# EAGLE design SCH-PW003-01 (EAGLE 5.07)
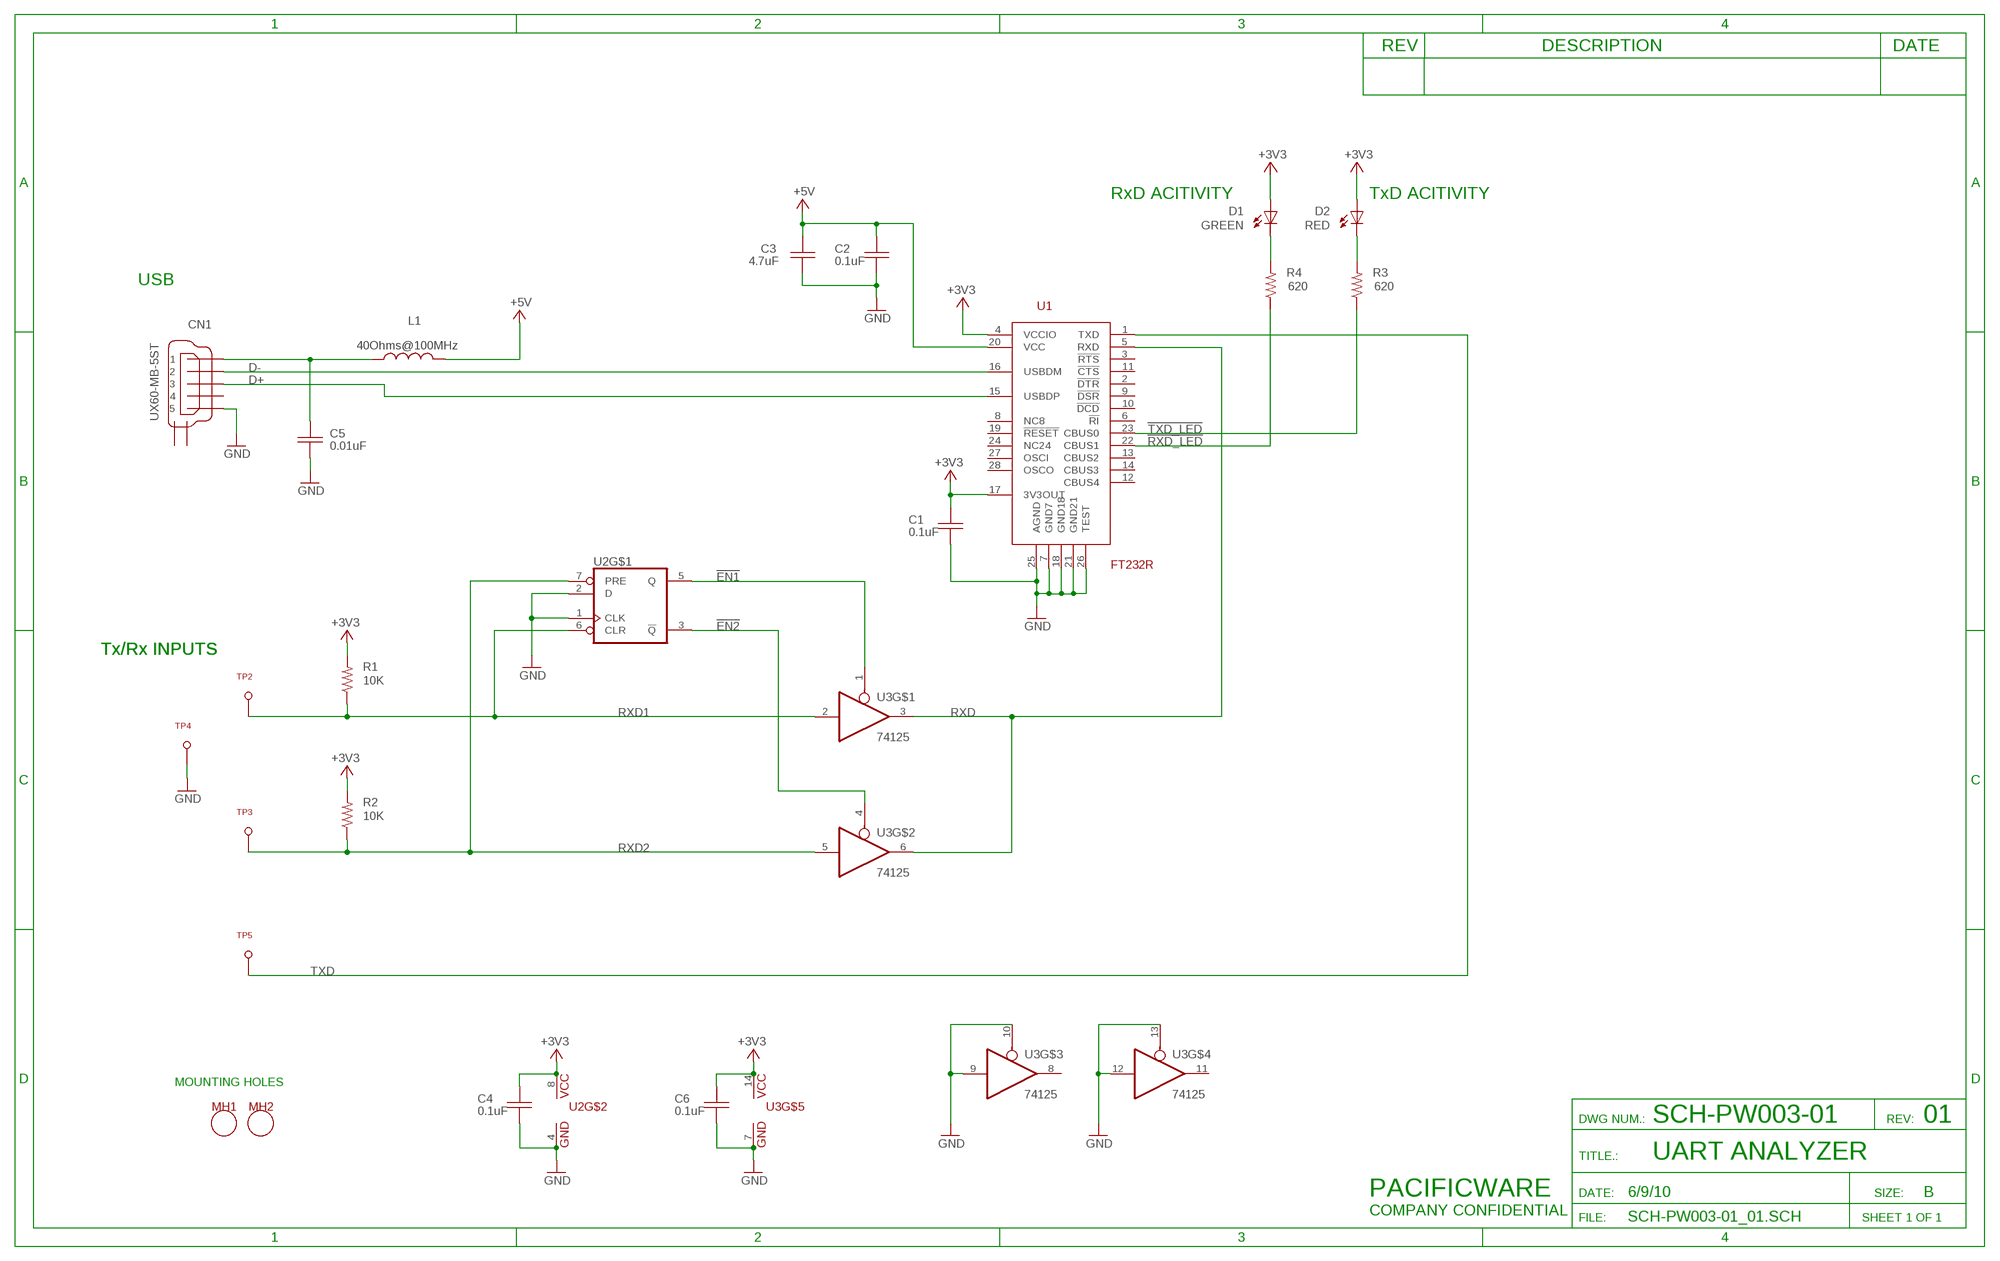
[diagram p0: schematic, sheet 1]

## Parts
C1  0.1uF  CAP-0805  [C0805]
C2  0.1uF  CAP-0805  [C0805]
C3  4.7uF  CAP-0805  [C0805]
C4  0.1uF  CAP-0805  [C0805]
C5  0.01uF  CAP-0805  [C0805]
C6  0.1uF  CAP-0805  [C0805]
CN1  UX60-MB-5ST  [UX60-MB-5ST]
D1  GREEN  LED0805  [0805LED]
D2  RED  LED0805  [0805LED]
L1  40Ohms@100MHz  IND-0805  [R0805]
MH1  HOLE_MTG_125NP  [HOLE_125NP]
MH2  HOLE_MTG_125NP  [HOLE_125NP]
R1  10K  RES-0805  [R0805]
R2  10K  RES-0805  [R0805]
R3  620  RES-0805  [R0805]
R4  620  RES-0805  [R0805]
TP2  TP_039  [HOLE_039_P]
TP3  TP_039  [HOLE_039_P]
TP4  TP_039  [HOLE_039_P]
TP5  TP_039  [HOLE_039_P]
U1  FT232R  [SSOP28]
U2  NL17SZ74  [US8]
U3  74125  [TSSOP14]

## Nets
!EN1: U2.5(Q) U3.1(OE)
!EN2: U2.3(!Q) U3.4(OE)
!RXD_LED: R4.1 U1.22(CBUS1)
!TXD_LED: R3.1 U1.23(CBUS0)
+3V3 [15mil]: C1.1 C4.1 C6.1 D1.1(A) D2.1(A) R1.2 R2.2 U1.4(VCCIO) U1.17(3V3OUT) U2.8(VCC) U3.14(VCC)
+5V [15mil]: C2.1 C3.1 L1.2 U1.20(VCC)
D+: CN1.3 U1.15(USBDP)
D-: CN1.2 U1.16(USBDM)
GND: C1.2 C2.2 C3.2 C4.2 C5.2 C6.2 CN1.5 TP4.1 U1.7(GND7) U1.18(GND18) U1.21(GND21) U1.25(AGND) U1.26(TEST) U2.1(CLK) U2.2(D) U2.4(GND) U3.7(GND) U3.9(I) U3.10(OE) U3.12(I) U3.13(OE)
N$1: C5.1 CN1.1 L1.1
N$2: D1.2(C) R4.2
N$5: D2.2(C) R3.2
RXD: U1.5(RXD) U3.3(O) U3.6(O)
RXD1: R1.1 TP2.1 U2.6(CLR) U3.2(I)
RXD2: R2.1 TP3.1 U2.7(PRE) U3.5(I)
TXD: TP5.1 U1.1(TXD)
Unconnected: CN1.4 CN1.6 CN1.7 U1.2(!DTR) U1.3(!RTS) U1.6(!RI) U1.8(NC8) U1.9(!DSR) U1.10(!DCD) U1.11(!CTS) U1.12(CBUS4) U1.13(CBUS2) U1.14(CBUS3) U1.19(!RESET) U1.24(NC24) U1.27(OSCI) U1.28(OSCO) U3.8(O) U3.11(O)

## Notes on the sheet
- REV | DESCRIPTION | DATE
- RxD ACITIVITY | TxD ACITIVITY
- USB
- Tx/Rx INPUTS | Tx/Rx INPUTS
- MOUNTING HOLES
- DWG NUM.: | SCH-PW003-01 | REV: | 01
- TITLE.: | UART ANALYZER
- PACIFICWARE | DATE: | 6/9/10 | SIZE: | B
- COMPANY CONFIDENTIAL
- FILE: | SCH-PW003-01_01.SCH | SHEET 1 OF 1

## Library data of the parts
C1-C6 = Pacificware:CAP-0805
CN1 = Pacificware:UX60-MB-5ST
D1 D2 = Pacificware:LED0805
L1 = Pacificware:IND-0805
MH1 MH2 = Pacificware:HOLE_MTG_125NP
R1-R4 = Pacificware:RES-0805
TP2-TP5 = Pacificware:TP_039
U1 = Pacificware:FT232R: FTDI FT232R, USB UART ICm, SSOP28
U2 = Pacificware:NL17SZ74: Single Gate D-FlopFlop
U3 = Pacificware:74125

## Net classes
1 20mil: width 0.508 mm
2 15mil: width 0.381 mm

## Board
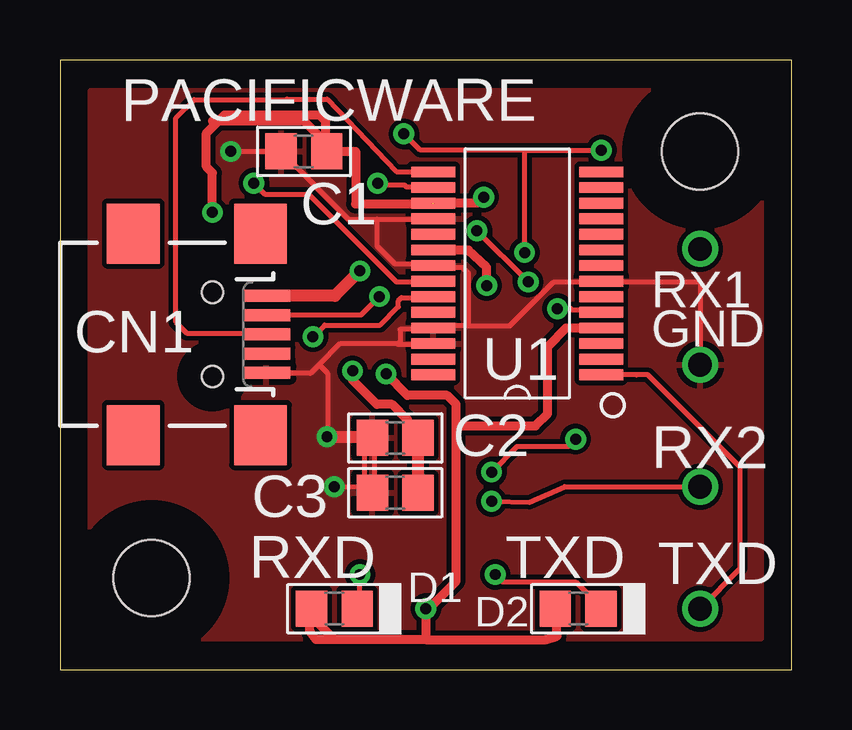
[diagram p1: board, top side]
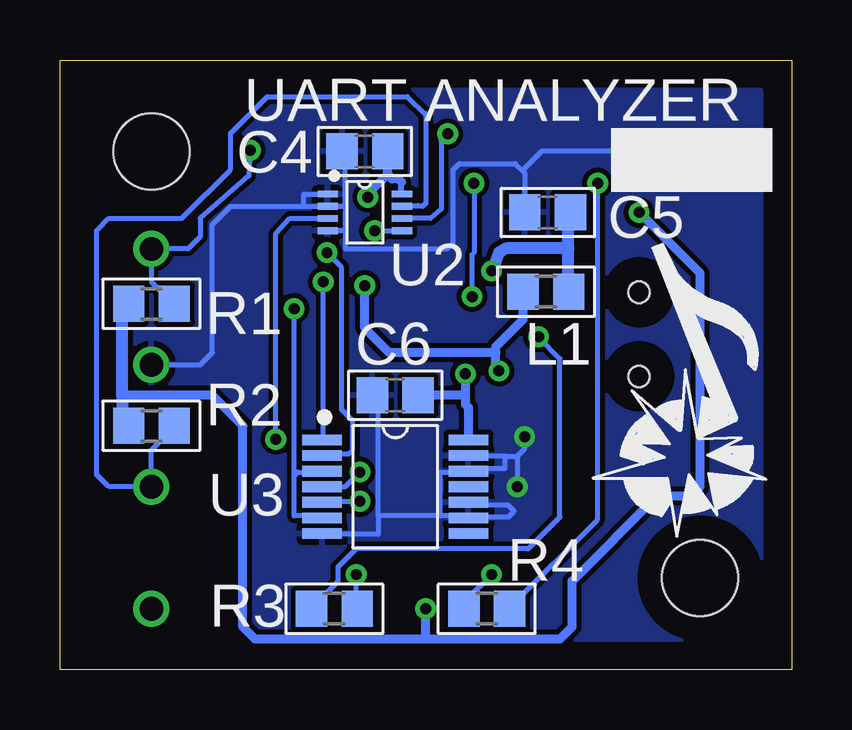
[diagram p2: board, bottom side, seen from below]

Size 30.48 x 25.4 mm. Coordinates in mm from the lower left corner, seen from the top.
Outline: 0,0 30.48,0 30.48,25.4 0,25.4 0,0
Copper layers (1*16): Top 0.035mm / dielectric 1.5mm / Bottom 0.035mm
Design rules "default *": minimum track width 8mil, minimum drill 18mil, track to track 8mil, track to pad 8mil, pad to pad 8mil, via to via 8mil, smd to smd 8mil, copper to edge 40mil, drill to drill 8mil, minimum pad ring 10mil, minimum via ring 8mil, stop-mask expansion 4mil, vias tented up to drill 0mil, thermal gap 10mil

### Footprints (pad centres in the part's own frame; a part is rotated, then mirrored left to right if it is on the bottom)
C0805 = smd 1.3 x 1.5: 1 -0.95,0; 2 0.95,0
UX60-MB-5ST = smd 2 x 0.5: 1 2.25,1.6; 2 2.25,0.8; 3 2.25,0; 4 2.25,-0.8; 5 2.25,-1.6 | smd 2.2 x 2.5: 6 -3.3,-4.2; 7 -3.3,4.2; 8 2,4.2; 9 2,-4.2 | hole 0.889: 0,1.753; 0,-1.753
0805LED = smd 1.3 x 1.5: 1 -0.95,0; 2 0.95,0
R0805 = smd 1.3 x 1.5: 1 -0.95,0; 2 0.95,0
HOLE_125NP = hole 3.175: 0,0
HOLE_039_P = drill 0.991 round: 1 0,0
SSOP28 = smd 0.45 x 1.82: 1 -4.225,-3.5; 2 -3.575,-3.5; 3 -2.925,-3.5; 4 -2.275,-3.5; 5 -1.625,-3.5; 6 -0.975,-3.5; 7 -0.325,-3.5; 8 0.325,-3.5; 9 0.975,-3.5; 10 1.625,-3.5; 11 2.275,-3.5; 12 2.925,-3.5; 13 3.575,-3.5; 14 4.225,-3.5; 15 4.225,3.5; 16 3.575,3.5; 17 2.925,3.5; 18 2.275,3.5; 19 1.625,3.5; 20 0.975,3.5; 21 0.325,3.5; 22 -0.325,3.5; 23 -0.975,3.5; 24 -1.625,3.5; 25 -2.275,3.5; 26 -2.925,3.5; 27 -3.575,3.5; 28 -4.225,3.5
US8 = smd 0.279 x 0.838: 1 -0.762,-1.549; 2 -0.254,-1.549; 3 0.254,-1.549; 4 0.762,-1.549; 5 0.762,1.549; 6 0.254,1.549; 7 -0.254,1.549; 8 -0.762,1.549
TSSOP14 = smd 0.45 x 1.65: 1 -1.95,-3.05; 2 -1.3,-3.05; 3 -0.65,-3.05; 4 0,-3.05; 5 0.65,-3.05; 6 1.3,-3.05; 7 1.95,-3.05; 8 1.95,3.05; 9 1.3,3.05; 10 0.65,3.05; 11 0,3.05; 12 -0.65,3.05; 13 -1.3,3.05; 14 -1.95,3.05

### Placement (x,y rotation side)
C1  10.16,21.59 180 top
C2  13.97,9.65 180 top
C3  13.97,7.37 180 top
C4  17.78,21.59 180 bottom
C5  10.16,19.05 180 bottom
C6  16.51,11.43 180 bottom
CN1  6.35,13.97 0 top
D1  11.43,2.54 0 top
D2  21.59,2.54 0 top
DRILEGEND  [DRILEGEND]  not placed on the board
L1  10.24,15.75 180 bottom
MH1  3.81,3.81 0 top
MH2  26.67,21.59 0 top
R1  26.67,15.24 180 bottom
R2  26.67,10.16 180 bottom
R3  19.05,2.54 0 bottom
R4  12.7,2.54 180 bottom
TP2  26.67,17.53 0 top
TP3  26.67,7.62 0 top
TP4  26.67,12.7 0 top
TP5  26.67,2.54 0 top
U1  19.05,16.51 90 top
U2  17.78,19.05 270 bottom
U3  16.51,7.62 270 bottom
U$1  [NOTE-SM]  4.32,9.45 0 bottom
U$2  [TITLE_BLOCK]  not placed on the board

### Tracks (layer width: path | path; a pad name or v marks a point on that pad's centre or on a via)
!EN1  (via drill 0.46)
  Top 0.203: v19.51,16.15 v17.37,18.29
  Bottom 0.203: v19.51,16.15 19.51,9.6 U3.1 | v17.37,18.29 U2.5
!EN2  (via drill 0.46)
  Top 0.203: v21.49,9.6 21.18,9.3 19.05,9.3 v17.98,8.23
  Bottom 0.203: v21.49,9.6 21.49,18.16 20.9,18.8 U2.3 | v17.98,8.23 18.59,7.62 U3.4
!RXD_LED  (via drill 0.46)
  Top 0.203: v8.08,20.27 8.53,19.81 10.36,19.81 14.02,16.15 15.54,16.15 U1.22
  Bottom 0.203: v8.08,20.27 8.08,6.25 11.73,2.59 R4.1
!TXD_LED  (via drill 0.46)
  Top 0.203: U1.23 15.51,15.49 14.22,15.49 14.1,15.37 14.1,15.11 13.34,14.35 11.02,14.35 v10.54,13.87
  Bottom 0.203: R3.1 19.96,2.59 18.9,3.66 18.9,4.27 18.14,5.03 10.97,5.03 9.65,6.35 9.65,12.95 10.54,13.84 v10.54,13.87
+3V3  (via drill 0.46)  (1 unrouted)
  Top 0.381: 15.54,19.41 12.32,19.41 12.32,21.59 11.43,21.59 | v6.35,19.05 6.35,20.7 6.1,20.95 6.1,22.35 6.48,22.73 | 6.48,22.73 6.86,23.11 10.79,23.11 11.05,22.86 11.05,21.65 | 10.41,2.54 10.41,1.6 10.67,1.25 11.43,1.25 | 15.24,1.25 11.43,1.25 | 15.24,1.25 20.24,1.25 20.7,1.4 20.7,2.48 D2.1 | 15.24,1.25 v15.24,2.54 15.37,2.54 16.51,3.68 16.51,10.29 | 16.51,10.29 16.51,11.05 16.13,11.43 14.48,11.43 v13.59,12.32 | U1.4 21.09,14.23 20.32,13.46 20.32,10.67 19.81,10.16 16.64,10.16 16.51,10.29 | U1.17 17.4,19.43 v17.65,19.68 | D1.1 10.16,2.54 11.43,1.27 11.43,1.25 | 11.43,21.59 10.16,22.86 6.35,22.86 6.48,22.73 | 11.43,21.59 C1.1
  Bottom 0.254: 16.26,20.32 16.26,19.84 U2.8
  Bottom 0.381: 16.83,20.64 C4.1 | 16.83,20.64 16.64,20.45 16.38,20.45 16.26,20.32 | 27.89,11.43 24.13,11.43 22.86,10.16 22.86,1.78 22.35,1.27 15.24,1.27 | v6.35,19.05 3.81,16.51 3.81,7.62 4.19,7.24 5.59,7.24 9.14,3.68 9.14,1.78 9.65,1.27 15.24,1.27 | 15.24,1.27 v15.24,2.54 | U3.14 13.46,10.92 13.59,11.05 13.59,11.43 | v17.65,19.68 17.65,19.82 16.83,20.64 | v13.59,12.32 13.59,11.43 | 13.59,11.43 C6.1 | R1.2 27.94,15.24 27.89,15.09
  Bottom 0.508: 27.74,15.24 27.89,15.09 27.89,11.43 27.89,10.36 27.74,10.21 R2.2
+5V  (via drill 0.46)
  Top 0.381: v12.19,12.45 12.19,12.06 13.21,11.05 13.84,11.05 14.48,10.41 14.48,10.09 C2.1 | v17.78,16 17.78,16.76 17.02,17.48 15.59,17.48 U1.20
  Top 0.508: 14.78,7.47 14.78,7.77 C3.1 | C2.1 14.94,10.06 14.94,8.08 C3.1 | C3.1 15.24,7.62
  Bottom 0.381: L1.2 11.19,14.6 12.32,13.46 12.32,13.21 | 12.32,13.21 12.32,12.57 v12.19,12.45 | 12.32,13.21 16.76,13.21 17.78,14.22 v17.78,16
  Bottom 0.508: L1.2 11.43,15.24
D+
  Top 0.203: U1.15 15.54,20.75 14.02,20.75 11.12,23.77 9.45,23.77 9.42,23.75 5.59,23.75 4.83,22.99 4.83,14.48 5.28,14.02 8.53,14.02 CN1.3
D-  (via drill 0.46)
  Top 0.203: U1.16 15.54,20.12 14.43,20.12 14.35,20.19 13.31,20.19 v13.23,20.27 | CN1.2 8.69,14.78 12.55,14.78 v13.31,15.54
  Bottom 0.203: v13.23,20.27 13.21,20.24 13.21,17.4 13.31,17.3 v13.31,15.54
GND  (via drill 0.46)
  Top 0.203: 13.21,18.77 15.54,18.77 U1.18 | 15.7,13.72 U1.26 15.54,13.56 14.07,13.56 14.05,13.59 11.68,13.59 10.79,12.7 | 13.11,10.06 13.11,7.92 C3.2 12.7,7.62 | CN1.5 8.69,12.34 10.44,12.34 10.79,12.7 | 17.02,14.33 18.75,14.33 20.57,16.15 22.4,16.15 U1.7 22.55,16.15 26.67,16.15 TP4.1 | 17.02,14.33 15.7,14.33 U1.25 15.7,14.17 14.17,14.17 14.17,13.66 | 17.02,14.33 17.02,16.51 16.76,16.76 15.7,16.76 U1.21 15.54,16.92 13.95,16.92 13.21,17.65 13.21,18.77 | v11.12,9.7 11.18,10.26 11.18,12.32 10.79,12.7 | v7.11,21.59 C1.2 9.3,21.49 12.01,18.77 13.21,18.77 | 12.7,7.62 12.7,10.16 C2.2 | v11.43,7.62 12.7,7.62
  Top 0.508: v11.12,9.7 12.97,9.7
  Bottom 0.203: 13.41,8.84 U3.13 13.43,8.89 11.94,8.89 | U3.9 13.41,6.4 | U3.10 13.41,6.86 11.81,6.86 11.56,6.6 11.81,6.35 13.43,6.35 U3.9 | 18.59,19.3 18.59,21.49 C4.2 | 18.59,19.3 18.59,18.29 | 18.59,18.29 U2.4 | 18.59,19.3 U2.2 20.32,19.3 | 18.59,18.29 18.59,17.53 14.35,17.53 14.1,17.78 14.1,20.83 13.84,21.08 11.51,21.08 11.12,20.7 11.12,19.05 C5.2 | 17.53,11.43 C6.2 17.37,11.43 17.22,11.28 17.22,6.4 | 17.22,6.4 17.22,5.64 19.51,5.64 U3.7 | 14.63,6.4 17.22,6.4 | 14.63,6.4 13.56,6.4 U3.9 | 14.63,6.4 14.63,8.23 13.56,8.23 U3.12 13.41,8.38 11.94,8.38 11.94,8.89 | v11.12,9.7 11.12,9.2 11.43,8.89 | 11.94,8.89 11.43,8.89 | U2.1 20.32,19.81 20.32,19.3 | 20.32,19.3 23.37,19.3 24.13,18.54 24.13,13.21 24.64,12.7 TP4.1 | v7.11,21.59 10.41,21.59 11.18,20.83 | 11.43,8.89 v11.43,7.62
  pour Top: 1.27,24.13 29.21,24.13 29.21,1.27 1.27,1.27
  pour Bottom: 1.27,24.13 29.21,24.13 29.21,1.27 1.27,1.27
N$1  (via drill 0.46)
  Top 0.203: 8.56,15.57 CN1.1
  Top 0.508: 8.56,15.57 11.46,15.57 v12.5,16.61
  Bottom 0.203: 9.3,19.05 C5.1
  Bottom 0.381: 12.34,16.97 v12.5,16.61 | L1.1 9.3,15.79
  Bottom 0.508: 9.3,17.55 9.3,19.05 | 12.34,16.97 12.19,17.37 11.89,17.55 9.3,17.55 | 9.3,15.79 9.3,17.55
N$2  (via drill 0.46)
  Top 0.203: v12.5,3.96 12.5,2.59 D1.2
  Bottom 0.203: v12.5,3.96 13.56,2.9 13.56,2.59 R4.2
N$5  (via drill 0.46)
  Top 0.203: v18.14,3.96 18.44,3.66 21.49,3.66 22.55,2.59 D2.2
  Bottom 0.203: v18.14,3.96 18.14,2.59 R3.2
RXD  (via drill 0.46)
  Top 0.203: 22.4,14.78 U1.5 22.45,14.99 21.34,14.99 21.29,15.04 v20.73,15.04
  Bottom 0.203: 20.73,8.08 20.73,6.4 19.66,6.4 U3.6 | 20.73,8.08 20.57,8.23 19.66,8.23 U3.3 | 20.73,8.08 v20.73,15.04
RXD1  (via drill 0.46)
  Top 0.203: v19.36,17.37 19.36,21.64 | 19.36,21.64 15.01,21.64 v14.33,22.33 | 19.36,21.64 v22.55,21.64
  Bottom 0.203: v19.36,17.37 18.75,16.76 18.75,10.82 18.29,10.36 18.29,9.14 18.44,8.99 19.51,8.99 U3.2 | U2.6 15.04,18.8 14.61,19.18 14.61,22.05 v14.33,22.33 | R1.1 25.76,15.24 26.67,16.15 TP2.1 25.15,17.53 24.64,18.03 24.64,18.8 22.61,20.57 v22.55,21.64
RXD2  (via drill 0.46)
  Top 0.203: v17.98,7.01 U3.5 21.03,7.62 TP3.1
  Bottom 0.203: v17.98,7.01 19.51,7.01 U3.5 | U2.7 15.37,19.3 15.24,19.43 15.24,23.11 | R2.1 25.76,10.06 26.67,9.14 TP3.1 28.45,7.62 28.96,8.13 28.96,18.29 28.45,18.8 25.4,18.8 23.37,20.83 23.37,22.35 21.84,23.88 16,23.88 15.24,23.11 | 15.24,23.11 15.24,23.16
TXD
  Top 0.203: U1.1 24.02,12.29 24.03,12.29 24.49,12.29 28.35,8.43 28.35,4.22 TP5.1

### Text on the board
tNames: PACIFICWARE | RX1 | GND | RX2 | RXD | TXD | TXD
bNames: UART ANALYZER
Measures: 1.00 | 0 | 0 | 1.20
DrillLgnd: NOTES: | 1. MATERIAL: FR-4. | 2. 1 OZ COPPER CLAD MIN ON EXTERNAL LAYERS | 3. MIN ANNULAR RING 0.001 INCHES. | 4. SOLDERMASK: SMOBC, LIQUID PHOTO-IMAGABLE, GREEN. | 5. SURFACE FINISH: HASL. | 6. SILKSCREEN: WHITE, NON-CONDUCTIVE EPOXY INK. | 7. VENDOR LOGO, DATE CODE TO BE ETCHED ON SOLDER SIDE. | 8. BOARD SHALL MEET IPC-A-600, CLASS 1. | 9. 0.018 VIAS HAVE TOLERANCE +0/-0.018 | LAYER STACKUP | LAYER 1 (CMP), SIGNAL | 0.062 +/- 0.007 | LAYER 2 (SOL), SIGNAL | UNLESS OTHERWISE SPECIFIED: | ALL DIMENSIONS IN INCHES. | PCB, UART ANALYZER | TOLERANCE IS +/- 0.005 | PCB-PW003-01 | 01 | PACIFICWARE | 6/9/10 | COMPANY CONFIDENTIAL | 1 OF 1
